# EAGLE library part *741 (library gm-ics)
OP AMP
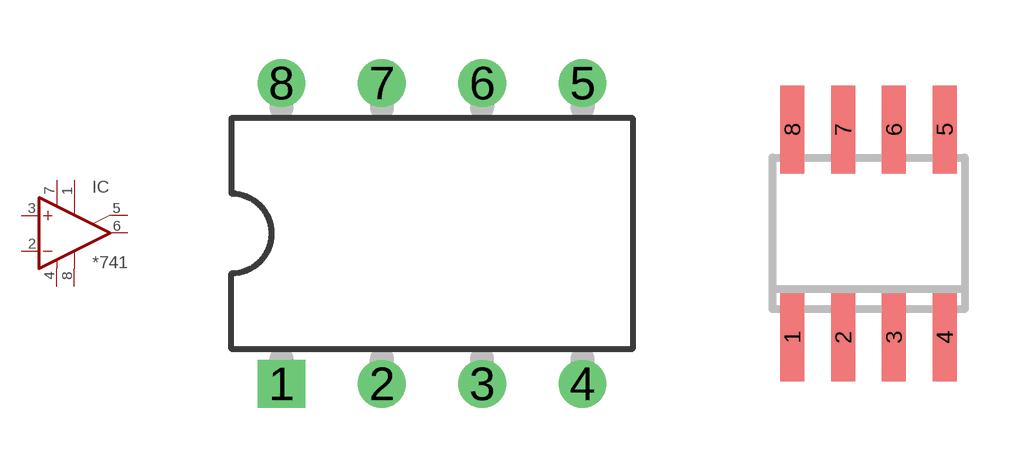
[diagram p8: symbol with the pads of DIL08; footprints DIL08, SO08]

Designator prefix IC

## LM741P, uA741P  [DIL08]
1  ON1  pas
2  -IN  in
3  +IN  in
4  V-  pwr
5  ON2  pas
6  OUT  out
7  V+  pwr
8  OPT  pas

## LM741D, uA741D  [SO08]
Pads as for DIL08

## Footprint DIL08 (pad centres in mm)
Dual In Line Package
drill 0.7 square: 1 -3.81,-3.81
drill 0.7 round: 2 -1.27,-3.81; 3 1.27,-3.81; 4 3.81,-3.81; 5 3.81,3.81; 6 1.27,3.81; 7 -1.27,3.81; 8 -3.81,3.81

## Footprint SO08 (pad centres in mm)
Small Outline Package 8 NS Package M08A
smd 0.6 x 2.2: 1 -1.905,-2.6; 2 -0.635,-2.6; 3 0.635,-2.6; 4 1.905,-2.6; 5 1.905,2.6; 6 0.635,2.6; 7 -0.635,2.6; 8 -1.905,2.6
